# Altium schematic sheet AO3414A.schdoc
size 127 x 101 mm
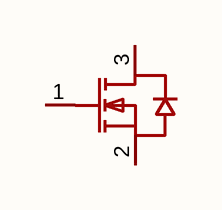
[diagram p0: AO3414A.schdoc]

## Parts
Q?  ao3414a  [SOT-23-3_L2.9-W1.3-P0.95-LS2.4-BR]  (value not drawn)

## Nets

Not connected (* = marked no-connect by the designer): Q? 1(G) 2(S) 3(D)

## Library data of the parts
Q? = ao3414a: 数量:1个N沟道;漏源电压(Vdss):20V;连续漏极电流(Id):4.2A;导通电阻(RDS(on)):23mΩ@4.5V;耗散功率(Pd):1.4W;阈值电压(Vgs(th)):600mV;; Manufacturer: UMW(友台半导体); AddInBom: yes; ModelId: c62791f0466c4ae2a892c056b845b0ca; ModelName: SOT-23-3P_L2.9-W1.3-H1.0-LS2.4-P0.95; ModelTransform: 98.425,114.173,0,180,0,0,0.0005,-0.0005,0; Number: 1个N沟道; Drain to Source Voltage: 20V; Current - Continuous Drain(Id): 4.2A; Pd - Power Dissipation: 1.4W; Gate Threshold Voltage (Vgs(th)): 600mV; Gate Charge(Qg): 1.6nC@4.5V; Input Capacitance(Ciss): 436pF; Reverse Transfer Capacitance (Crss@Vds): 44pF; Type: N沟道; Output Capacitance(Coss): 66pF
